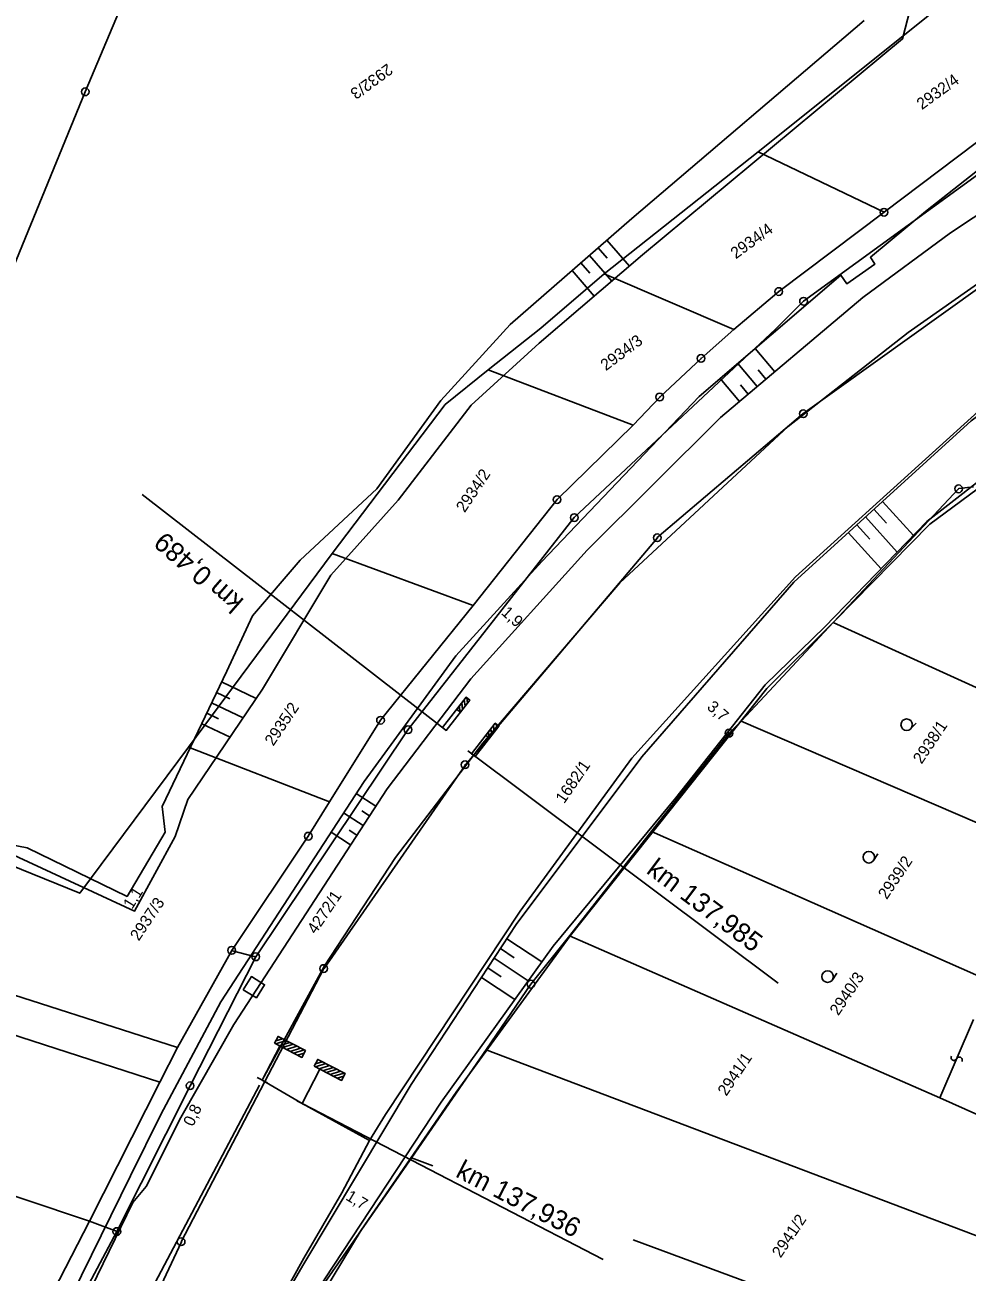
# Model space of a CAD drawing. Extents: x -658910 to -658078, y -1170373 to -1169331.
# Drawn here: x -658303.7 to -658181.4, y -1169622.6 to -1169460.8 of the extents above; entities that cross this region are included whole.
import ezdxf

# ---------------------------------------------------------------- set-up
doc = ezdxf.new("R2010")
doc.units = 0
for name, color, linetype in [('Vrstva 1', 7, 'Continuous'), ('Vrstva 10', 7, 'Continuous'), ('Vrstva 11', 7, 'Continuous'), ('Vrstva 12', 7, 'Continuous'), ('Vrstva 16', 7, 'Continuous'), ('Vrstva 22', 7, 'Continuous'), ('Vrstva 23', 7, 'Continuous'), ('Vrstva 26', 7, 'Continuous'), ('Vrstva 27', 7, 'Continuous'), ('Vrstva 8', 7, 'Continuous'), ('Vrstva 9', 7, 'Continuous')]:
    doc.layers.add(name, color=color, linetype=linetype)

msp = doc.modelspace()

# ---------------------------------------------------------------- linework, layer by layer
at = {"layer": 'Vrstva 1'}
for p, q in [((-658202.691, -1169496.621), (-658202.591, -1169496.621)), ((-658182.481, -1169520.9), (-658198.77, -1169538.248)), ((-658182.57, -1169520.961), (-658182.47, -1169520.961)), ((-658180.582, -1169520.72), (-658182.481, -1169520.9)), ((-658232.448, -1169524.699), (-658232.348, -1169524.699)), ((-658198.77, -1169538.248), (-658210.711, -1169551.06)), ((-658210.711, -1169551.06), (-658212.27, -1169552.609)), ((-658254.03, -1169552.23), (-658253.93, -1169552.23)), ((-658212.27, -1169552.609), (-658222.332, -1169565.349)), ((-658212.359, -1169552.67), (-658212.259, -1169552.67)), ((-658222.332, -1169565.349), (-658232.981, -1169578.919)), ((-658232.981, -1169578.919), (-658238.02, -1169585.24)), ((-658273.78, -1169581.691), (-658273.68, -1169581.691)), ((-658238.02, -1169585.24), (-658243.77, -1169593.679)), ((-658238.07, -1169585.24), (-658237.97, -1169585.24)), ((-658243.77, -1169593.679), (-658253.461, -1169607.728)), ((-658282.3, -1169598.42), (-658282.2, -1169598.42)), ((-658253.461, -1169607.728), (-658266.16, -1169625.929)), ((-658291.812, -1169617.34), (-658291.712, -1169617.34))]:
    msp.add_line(p, q, dxfattribs=at)
for points in [[(-658206.289, -1169500.25), (-658202.641, -1169496.621), (-658158.738, -1169464.74), (-658125.93, -1169449.82)], [(-658387.09, -1169803.74), (-658379.66, -1169787.031), (-658371.41, -1169770.08), (-658363.031, -1169753.09), (-658350.949, -1169718.6), (-658329.91, -1169685.09), (-658309.48, -1169652.309), (-658298.289, -1169629.6), (-658291.762, -1169617.34), (-658282.25, -1169598.42), (-658273.73, -1169581.691), (-658253.98, -1169552.23), (-658232.398, -1169524.699), (-658206.289, -1169500.25)]]:
    msp.add_lwpolyline(points, dxfattribs=at)
for centre in [(-658202.641, -1169496.621), (-658182.52, -1169520.961), (-658232.398, -1169524.699), (-658253.98, -1169552.23), (-658212.309, -1169552.67), (-658273.73, -1169581.691), (-658238.02, -1169585.24), (-658282.25, -1169598.42), (-658291.762, -1169617.34)]:
    msp.add_circle(centre, 0.499, dxfattribs=at)
at = {"layer": 'Vrstva 10'}
for points in [[(-658276.584, -1169590.485), (-658256.68, -1169559.896), (-658245.84, -1169545.609), (-658230.723, -1169528.912), (-658213.416, -1169511.695), (-658194.942, -1169496.127), (-658183.568, -1169487.746), (-658168.721, -1169477.939), (-658152.051, -1169468.653), (-658137.192, -1169462.524), (-658116.058, -1169454.53), (-658100, -1169450.302)], [(-658272.892, -1169597.713), (-658264.789, -1169582.869), (-658255.603, -1169568.821), (-658244.243, -1169553.949), (-658226.467, -1169533.172), (-658204.621, -1169512.867), (-658189.065, -1169500.683), (-658177.28, -1169492.406), (-658159.62, -1169480.938), (-658148.705, -1169475.017), (-658136.322, -1169469.204), (-658112.115, -1169460.739), (-658108.733, -1169459.765), (-658110.378, -1169454.042), (-658101.99, -1169451.722), (-658100, -1169450.993)], [(-658137.695, -1169456.646), (-658152.911, -1169463.386), (-658171.698, -1169473.069), (-658186.816, -1169484.99), (-658193.967, -1169490.9), (-658193.37, -1169491.788), (-658197.029, -1169494.358), (-658197.792, -1169493.244), (-658216.175, -1169508.98), (-658236.592, -1169530.379), (-658247.771, -1169542.617), (-658259.683, -1169558.947), (-658278.256, -1169587.533)], [(-658194.776, -1169460.194), (-658224.927, -1169485.893), (-658240.721, -1169499.622), (-658249.728, -1169509.51), (-658258.019, -1169520.955), (-658267.977, -1169530.234), (-658274.167, -1169537.438), (-658277.501, -1169544.636), (-658285.866, -1169562.195), (-658285.468, -1169565.535), (-658290.44, -1169573.844), (-658303.418, -1169567.527), (-658309.934, -1169566.284), (-658289.485, -1169575.785), (-658284.171, -1169566.065), (-658282.55, -1169561.267), (-658272.844, -1169546.971), (-658264.004, -1169532.154), (-658255.261, -1169522.447), (-658245.754, -1169510.106), (-658236.942, -1169502.039), (-658223.545, -1169490.595), (-658189.788, -1169462.569), (-658188.806, -1169458.731)], [(-658256.897, -1169602.161), (-658239.427, -1169575.771), (-658224.934, -1169555.9), (-658203.674, -1169532.371), (-658179.993, -1169510.94), (-658159.792, -1169495.061), (-658143.824, -1169485.141), (-658125.802, -1169475.437), (-658112.002, -1169468.967), (-658100, -1169464.008)], [(-658253.549, -1169598.254), (-658239.939, -1169577.516), (-658223.63, -1169555.733), (-658203.92, -1169533.073), (-658180.876, -1169512.128), (-658158.5, -1169495.23), (-658142.617, -1169485.149), (-658124.162, -1169475.476), (-658110.654, -1169469.183), (-658100, -1169464.754)], [(-658100, -1169474.017), (-658111.267, -1169478.843), (-658123.536, -1169484.929), (-658141.479, -1169493.669), (-658154.391, -1169501.045), (-658176.701, -1169517.474), (-658186.618, -1169525.185), (-658199.861, -1169538.886), (-658207.601, -1169546.414), (-658219.233, -1169561.048), (-658235.126, -1169580.291), (-658249.659, -1169600.535)], [(-658228.154, -1169488.698), (-658225.244, -1169492.046)], [(-658230.418, -1169490.666), (-658227.525, -1169493.995)], [(-658229.286, -1169489.682), (-658228.125, -1169491.017)], [(-658231.551, -1169491.65), (-658230.396, -1169492.978)], [(-658232.683, -1169492.634), (-658229.806, -1169495.943)], [(-658206.372, -1169505.76), (-658208.904, -1169502.756)], [(-658208.667, -1169507.693), (-658211.183, -1169504.707)], [(-658210.961, -1169509.626), (-658213.462, -1169506.658)], [(-658207.52, -1169506.727), (-658208.529, -1169505.528)], [(-658209.813, -1169508.66), (-658210.817, -1169507.469)], [(-658192.392, -1169522.595), (-658188.381, -1169527.008)], [(-658194.612, -1169524.613), (-658190.47, -1169529.17)], [(-658193.502, -1169523.604), (-658191.872, -1169525.398)], [(-658195.722, -1169525.622), (-658194.039, -1169527.473)], [(-658196.832, -1169526.63), (-658192.559, -1169531.332)], [(-658278.164, -1169546.026), (-658273.659, -1169548.172)], [(-658279.454, -1169548.735), (-658275.364, -1169550.683)], [(-658278.809, -1169547.381), (-658277.09, -1169548.2)], [(-658280.099, -1169550.089), (-658278.546, -1169550.829)], [(-658280.744, -1169551.443), (-658277.069, -1169553.194)], [(-658258.148, -1169562.15), (-658260.69, -1169560.497)], [(-658259.784, -1169564.665), (-658262.324, -1169563.012)], [(-658258.966, -1169563.408), (-658259.982, -1169562.747)], [(-658261.42, -1169567.18), (-658263.958, -1169565.528)], [(-658260.602, -1169565.922), (-658261.618, -1169565.262)], [(-658241.156, -1169579.37), (-658236.608, -1169582.354)], [(-658241.979, -1169580.624), (-658240.181, -1169581.804)], [(-658242.802, -1169581.878), (-658238.359, -1169584.793)], [(-658244.448, -1169584.386), (-658240.11, -1169587.233)], [(-658243.625, -1169583.132), (-658241.869, -1169584.285)], [(-658276.584, -1169590.485), (-658283.44, -1169602.541), (-658287.975, -1169611.492), (-658289.687, -1169613.574), (-658302.78, -1169640.536), (-658308.513, -1169652.938), (-658311.735, -1169652.624), (-658329.784, -1169644.735), (-658339.953, -1169641.872), (-658339.466, -1169639.877), (-658334.347, -1169641.667), (-658319.785, -1169646.697), (-658309.854, -1169650.681), (-658305.208, -1169641.097), (-658290.001, -1169610.092), (-658286.058, -1169602.153), (-658278.256, -1169587.533)], [(-658412.34, -1169868.25), (-658390.58, -1169825.61), (-658346.68, -1169740.23), (-658319.39, -1169686.96), (-658299.95, -1169648.82), (-658273.229, -1169598.35)], [(-658333.115, -1169751.576), (-658323.796, -1169728.025), (-658308.485, -1169695.615), (-658294.271, -1169668.043), (-658278.157, -1169639.847), (-658267.473, -1169621.543), (-658253.549, -1169598.254)], [(-658258.99, -1169605.547), (-658267.725, -1169600.707), (-658272.892, -1169597.713)], [(-658249.659, -1169600.535), (-658264.767, -1169623.458), (-658274.587, -1169639.486), (-658284.944, -1169658.621), (-658291.388, -1169672.25), (-658302.068, -1169694.842), (-658312.164, -1169713.774), (-658318.886, -1169726.345), (-658324.9, -1169737.364), (-658333.115, -1169751.576)], [(-658258.99, -1169605.547), (-658256.897, -1169602.161)], [(-658354.813, -1169800), (-658338.217, -1169761.133), (-658328.016, -1169737.523), (-658311.372, -1169701.327), (-658294.326, -1169669.378), (-658287.561, -1169657.031), (-658267.485, -1169620.8), (-658262.54, -1169612.307), (-658258.99, -1169605.547)]]:
    msp.add_lwpolyline(points, dxfattribs=at)
at = {"layer": 'Vrstva 12'}
for points in [[(-658247.717, -1169599.265), (-658232.917, -1169578.969), (-658207.409, -1169546.852), (-658198.628, -1169538.138), (-658186.253, -1169525.541), (-658153.733, -1169501.492), (-658125.5, -1169487.513), (-658105.01, -1169477.535)], [(-658247.717, -1169599.265), (-658232.917, -1169578.969), (-658207.409, -1169546.852), (-658198.628, -1169538.138), (-658186.253, -1169525.541), (-658153.733, -1169501.492), (-658125.5, -1169487.513), (-658105.01, -1169477.535)], [(-658289.246, -1169696.288), (-658301.393, -1169693.156), (-658286.864, -1169663.622), (-658275.728, -1169643.056), (-658260.067, -1169617.171), (-658247.717, -1169599.265)], [(-658289.246, -1169696.288), (-658301.393, -1169693.156), (-658286.864, -1169663.622), (-658275.728, -1169643.056), (-658260.067, -1169617.171), (-658247.717, -1169599.265)]]:
    msp.add_lwpolyline(points, dxfattribs=at)
at = {"layer": 'Vrstva 16'}
msp.add_lwpolyline([(-658275.347, -1169585.954), (-658274.294, -1169584.253), (-658272.593, -1169585.306), (-658273.646, -1169587.007), (-658275.347, -1169585.954)], dxfattribs=at)
at = {"layer": 'Vrstva 22'}
for p, q in [((-658271.302, -1169592.905), (-658270.843, -1169592.017)), ((-658269.798, -1169592.558), (-658271.146, -1169592.986)), ((-658270.269, -1169592.314), (-658271.14, -1169592.59)), ((-658270.843, -1169592.017), (-658267.291, -1169593.856)), ((-658270.592, -1169593.273), (-658272.892, -1169597.713)), ((-658267.751, -1169594.744), (-658271.302, -1169592.905)), ((-658269.328, -1169592.801), (-658270.676, -1169593.229)), ((-658268.856, -1169593.046), (-658270.204, -1169593.474)), ((-658268.386, -1169593.289), (-658269.733, -1169593.717)), ((-658267.915, -1169593.533), (-658269.263, -1169593.961)), ((-658267.443, -1169593.777), (-658268.791, -1169594.205)), ((-658267.455, -1169594.174), (-658268.321, -1169594.449)), ((-658267.291, -1169593.856), (-658267.751, -1169594.744)), ((-658266.135, -1169595.899), (-658265.676, -1169595.011)), ((-658264.631, -1169595.552), (-658265.979, -1169595.98)), ((-658265.102, -1169595.308), (-658265.973, -1169595.584)), ((-658265.676, -1169595.011), (-658262.124, -1169596.85)), ((-658264.161, -1169595.795), (-658265.509, -1169596.223)), ((-658273.557, -1169597.368), (-658272.226, -1169598.057)), ((-658265.425, -1169596.267), (-658267.725, -1169600.707)), ((-658262.584, -1169597.738), (-658266.135, -1169595.899)), ((-658263.689, -1169596.04), (-658265.037, -1169596.468)), ((-658263.219, -1169596.283), (-658264.566, -1169596.711)), ((-658262.748, -1169596.527), (-658264.096, -1169596.955)), ((-658262.276, -1169596.771), (-658263.624, -1169597.199)), ((-658262.288, -1169597.168), (-658263.154, -1169597.443)), ((-658262.124, -1169596.85), (-658262.584, -1169597.738)), ((-658268.39, -1169600.362), (-658267.059, -1169601.051))]:
    msp.add_line(p, q, dxfattribs=at)
for points in [[(-658271.302, -1169592.905), (-658270.843, -1169592.017), (-658267.291, -1169593.856), (-658267.751, -1169594.744)], [(-658266.135, -1169595.899), (-658265.676, -1169595.011), (-658262.124, -1169596.85), (-658262.584, -1169597.738)]]:
    msp.add_lwpolyline(points, close=True, dxfattribs=at)
msp.add_lwpolyline([(-658272.892, -1169597.713), (-658267.725, -1169600.707), (-658228.647, -1169620.949)], dxfattribs=at)
at = {"layer": 'Vrstva 26'}
for p, q in [((-658246.887, -1169549.573), (-658246.993, -1169548.731)), ((-658246.562, -1169549.155), (-658246.668, -1169548.313)), ((-658246.236, -1169548.735), (-658246.317, -1169548.088)), ((-658247.654, -1169549.583), (-658247.654, -1169549.583)), ((-658247.654, -1169549.583), (-658247.18, -1169549.951)), ((-658247.64, -1169549.593), (-658247.643, -1169549.569)), ((-658247.221, -1169549.919), (-658247.318, -1169549.15)), ((-658243.115, -1169552.952), (-658243.221, -1169552.11)), ((-658242.79, -1169552.534), (-658242.896, -1169551.692)), ((-658242.464, -1169552.114), (-658242.545, -1169551.467)), ((-658243.882, -1169552.962), (-658243.882, -1169552.962)), ((-658243.882, -1169552.962), (-658243.408, -1169553.33)), ((-658243.868, -1169552.972), (-658243.871, -1169552.948)), ((-658243.449, -1169553.298), (-658243.546, -1169552.529)), ((-658245.485, -1169555.516), (-658245.485, -1169555.516))]:
    msp.add_line(p, q, dxfattribs=at)
for points in [[(-658288.453, -1169521.705), (-658249.257, -1169552.137)], [(-658249.493, -1169551.953), (-658246.427, -1169548.003), (-658245.953, -1169548.371), (-658249.02, -1169552.32), (-658249.493, -1169551.953)], [(-658245.721, -1169555.332), (-658242.655, -1169551.382), (-658242.181, -1169551.75), (-658245.248, -1169555.699), (-658245.721, -1169555.332)], [(-658205.952, -1169585.119), (-658246.228, -1169554.959)]]:
    msp.add_lwpolyline(points, dxfattribs=at)
for points in [[(-658245.953, -1169548.371), (-658247.18, -1169549.951), (-658247.654, -1169549.583), (-658246.427, -1169548.003)], [(-658242.181, -1169551.75), (-658243.408, -1169553.33), (-658243.882, -1169552.962), (-658242.655, -1169551.382)]]:
    msp.add_lwpolyline(points, close=True, dxfattribs=at)
at = {"layer": 'Vrstva 8'}
for p, q in [((-658295.909, -1169469.441), (-658295.809, -1169469.441)), ((-658192.241, -1169485.07), (-658192.141, -1169485.07)), ((-658192.241, -1169485.07), (-658192.141, -1169485.07)), ((-658205.909, -1169495.359), (-658205.809, -1169495.359)), ((-658215.991, -1169504.039), (-658215.891, -1169504.039)), ((-658221.359, -1169509.051), (-658221.259, -1169509.051)), ((-658221.675, -1169527.307), (-658202.732, -1169511.222)), ((-658202.732, -1169511.222), (-658202.632, -1169511.222)), ((-658202.732, -1169511.222), (-658202.632, -1169511.222)), ((-658234.671, -1169522.359), (-658234.571, -1169522.359)), ((-658246.525, -1169556.772), (-658221.575, -1169527.307)), ((-658221.675, -1169527.307), (-658221.575, -1169527.307)), ((-658257.589, -1169550.99), (-658257.489, -1169550.99)), ((-658264.867, -1169583.212), (-658246.525, -1169556.772)), ((-658246.625, -1169556.772), (-658246.525, -1169556.772)), ((-658266.96, -1169566.039), (-658266.86, -1169566.039)), ((-658276.902, -1169580.85), (-658276.802, -1169580.85)), ((-658264.967, -1169583.212), (-658264.867, -1169583.212)), ((-658264.967, -1169583.212), (-658264.867, -1169583.212)), ((-658283.467, -1169618.664), (-658283.367, -1169618.664))]:
    msp.add_line(p, q, dxfattribs=at)
for points in [[(-658202.732, -1169511.222), (-658165.92, -1169484.904), (-658139.581, -1169470.905), (-658095.97, -1169442.051)], [(-658308.539, -1169500.27), (-658295.859, -1169469.441), (-658284.391, -1169442.24)], [(-658211.672, -1169500.27), (-658205.859, -1169495.359), (-658192.191, -1169485.07), (-658166.07, -1169465.391), (-658163.68, -1169463.92), (-658162.129, -1169462.75), (-658139.891, -1169451.109), (-658133.059, -1169448.781), (-658125.75, -1169446.57)], [(-658182.059, -1169455.99), (-658186.52, -1169459.621), (-658208.531, -1169477.24), (-658192.191, -1169485.07)], [(-658228.5, -1169493.051), (-658208.531, -1169477.24)], [(-658211.672, -1169500.27), (-658228.5, -1169493.051), (-658236.719, -1169500.129)], [(-658282.48, -1169554.49), (-658296.57, -1169573.449), (-658331.68, -1169559.211), (-658312.48, -1169510.551), (-658308.539, -1169500.27)], [(-658314.059, -1169652.35), (-658295.309, -1169616), (-658286.199, -1169597.941), (-658283.891, -1169593.469), (-658276.852, -1169580.85), (-658266.91, -1169566.039), (-658264.172, -1169561.6), (-658257.539, -1169550.99), (-658245.52, -1169536.1), (-658234.621, -1169522.359), (-658224.73, -1169512.711), (-658221.309, -1169509.051), (-658215.941, -1169504.039), (-658211.672, -1169500.27)], [(-658236.719, -1169500.129), (-658243.551, -1169505.5), (-658224.73, -1169512.711)], [(-658243.551, -1169505.5), (-658249.129, -1169510), (-658263.828, -1169529.359), (-658245.52, -1169536.1)], [(-658263.828, -1169529.359), (-658282.48, -1169554.49), (-658264.172, -1169561.6)], [(-658157.32, -1169557.18), (-658198.809, -1169538.309)], [(-658210.75, -1169551.121), (-658163.25, -1169571.57)], [(-658178.398, -1169584.85), (-658222.371, -1169565.41)], [(-658283.891, -1169593.469), (-658338.34, -1169575.98)], [(-658184.961, -1169600.01), (-658233.02, -1169578.98)], [(-658286.199, -1169597.941), (-658340.34, -1169580.449)], [(-658276.902, -1169580.85), (-658273.78, -1169581.691)], [(-658283.417, -1169618.664), (-658264.917, -1169583.212)], [(-658180.57, -1169589.83), (-658184.961, -1169600.01), (-658173.84, -1169604.961), (-658172.262, -1169605.65)], [(-658243.809, -1169593.74), (-658179.391, -1169618.211)], [(-658295.309, -1169616), (-658347.898, -1169598.379)], [(-658253.5, -1169607.789), (-658250.732, -1169608.813)], [(-658295.309, -1169616), (-658291.712, -1169617.34)], [(-658224.734, -1169618.434), (-658181.91, -1169634.281)], [(-658340.286, -1169739.901), (-658283.367, -1169618.664)]]:
    msp.add_lwpolyline(points, dxfattribs=at)
for centre in [(-658295.859, -1169469.441), (-658192.191, -1169485.07), (-658192.191, -1169485.07), (-658205.859, -1169495.359), (-658215.941, -1169504.039), (-658221.309, -1169509.051), (-658202.682, -1169511.222), (-658202.682, -1169511.222), (-658234.621, -1169522.359), (-658221.625, -1169527.307), (-658257.539, -1169550.99), (-658246.575, -1169556.772), (-658266.91, -1169566.039), (-658276.852, -1169580.85), (-658264.917, -1169583.212), (-658264.917, -1169583.212), (-658283.417, -1169618.664)]:
    msp.add_circle(centre, 0.499, dxfattribs=at)
for centre, radius, start, end in [((-658183.113, -1169594.767), 0.376, 149.72436, 336.0355), ((-658182.424, -1169595.069), 0.377, 329.04832, 156.71154)]:
    msp.add_arc(centre, radius, start, end, dxfattribs=at)
at = {"layer": 'Vrstva 9'}
for p, q in [((-658188.707, -1169552.083), (-658188.026, -1169551.352)), ((-658193.54, -1169569.181), (-658192.988, -1169568.348)), ((-658198.881, -1169584.672), (-658198.338, -1169583.833))]:
    msp.add_line(p, q, dxfattribs=at)
for centre in [(-658189.256, -1169551.572), (-658194.166, -1169568.767), (-658199.511, -1169584.265)]:
    msp.add_circle(centre, 0.75, dxfattribs=at)

# ---------------------------------------------------------------- texts
at = {"layer": 'Vrstva 11'}
for s, rotation, p in [('1,9', 317.84374, (-658241.963, -1169537.164)), ('3,7', 318.98312, (-658215.28, -1169549.43)), ('1682/1', 55.59191, (-658233.706, -1169561.897)), ('1,1', 57.69229, (-658289.785, -1169575.603)), ('4272/1', 56.05972, (-658265.943, -1169578.836)), ('0,8', 65.36224, (-658281.858, -1169603.8)), ('1,7', 329.1251, (-658262.169, -1169613.148))]:
    msp.add_text(s, height=1.5, rotation=rotation, dxfattribs=at).set_placement(p)
at = {"layer": 'Vrstva 23'}
msp.add_text('km 137,936', height=2.5, rotation=332.61712, dxfattribs=at).set_placement((-658247.928, -1169610.166))
at = {"layer": 'Vrstva 27'}
for s, rotation, p in [('km 0,489', 138.98356, (-658275.137, -1169535.413)), ('km 137,985', 323.19685, (-658223.167, -1169570.74))]:
    msp.add_text(s, height=2.5, rotation=rotation, dxfattribs=at).set_placement(p)
at = {"layer": 'Vrstva 9'}
for s, rotation, p in [('2932/3', 215.98794, (-658256.648, -1169465.699)), ('2932/4', 35.98794, (-658187.277, -1169471.826)), ('2934/4', 35.98794, (-658211.426, -1169491.189)), ('2934/3', 36.74925, (-658228.292, -1169505.707)), ('2934/2', 56.1528, (-658246.615, -1169524.132)), ('2935/2', 56.1528, (-658271.453, -1169554.418)), ('2938/1', 56.1528, (-658187.312, -1169556.763)), ('2939/2', 56.1528, (-658191.841, -1169574.342)), ('2937/3', 56.1528, (-658288.914, -1169579.725)), ('2940/3', 56.1528, (-658198.117, -1169589.41)), ('2941/1', 56.1528, (-658212.659, -1169599.857)), ('2941/2', 56.1528, (-658205.612, -1169620.849))]:
    msp.add_text(s, height=1.5, rotation=rotation, dxfattribs=at).set_placement(p)

doc.saveas('drawing.dxf')
